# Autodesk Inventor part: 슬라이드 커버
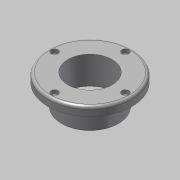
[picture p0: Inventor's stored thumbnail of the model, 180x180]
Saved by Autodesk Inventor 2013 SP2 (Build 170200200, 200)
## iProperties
Created: 2015-10
Part Number: 슬라이드 커버
Document SubType Name: Modeling
Designer: mdu
Density: 7.86 g/cm^3
Material: 강철, 연강
Mass: 598.523 g
Surface Area: 229.996 cm^2
Volume: 76.148 cm^3
Author: mdu
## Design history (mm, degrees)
sketch "스케치1"
  geometry: C1 r 47.5 at (0, 0); C2 r 32.5 at (0, 0); 1 further point
  constraints: 2 centre point, 2 coincident
  dimensions: "d33" = 95 diameter of C1; "d35" = 65 diameter of C2
extrude "돌출1" new body sketch "스케치1" distance "d0" = 10; taper "d1" = 0 deg
extrude "돌출2" join sketch "스케치1" distance "d2" = 25; taper "d3" = 0 deg
hole "구멍1" diameter "d6" = 50; stored, may be unused: countersink angle "d10" = 90 deg, drill point angle "d12" = 118 deg; dims "d4" = 10, "d5" = 10, "d7" = 6, "d8" = 4, "d9" = 2, "d11" = 8
sketch "스케치2" dims "d36" = 80
  geometry: 4 further points
  constraints: 2 coincident, 2 vertical alignment, 2 other
hole "구멍2" sketch "스케치2" at (0, 40) diameter "d13" = 4.5; stored, may be unused: countersink angle "d17" = 90 deg, drill point angle "d19" = 118 deg; dims "d14" = 6, "d15" = 8, "d16" = 4.4, "d18" = 8
fillet "모깎기1" dims "d23" = 3
chamfer "모따기1" distance "d24" = 1; stored, may be unused: second distance "d25" = 2, angle "d26" = 45 deg
sketch "스케치3"
  geometry: C1 r 25 at (0, 0); C2 r 30 at (0, 0); C3 r 26 at (0, 0) reference; 1 further point
  constraints: 2 centre point, 2 coincident
  dimensions: "d27" = 60 diameter of C2
extrude "돌출3" cut sketch "스케치3" distance "d28" = 3; taper "d29" = 0 deg
chamfer "모따기2" distance "d30" = 1; stored, may be unused: second distance "d31" = 2, angle "d32" = 45 deg
node "솔리드1"
pattern_circular "원형 패턴1" dims angle "d21" = 360 deg
